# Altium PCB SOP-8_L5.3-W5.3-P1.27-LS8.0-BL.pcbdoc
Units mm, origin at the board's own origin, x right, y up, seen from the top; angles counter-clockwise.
Board outline 18.2 x 21.99 mm, 2 copper layers (Top Layer, Bottom Layer), stack 0 mm thick; 1 components, 0 nets, 8 pads, 0 vias.
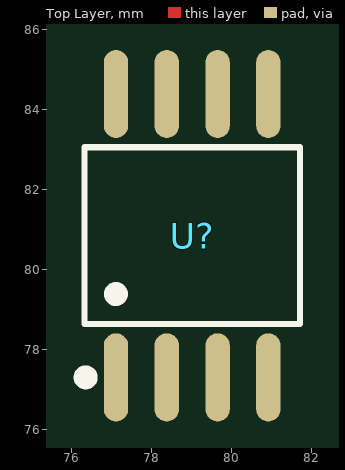
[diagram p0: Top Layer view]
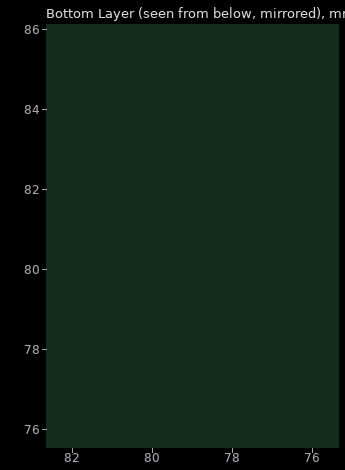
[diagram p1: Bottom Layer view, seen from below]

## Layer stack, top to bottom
Top Layer: signal copper (thickness not stored)
Bottom Layer: signal copper (thickness not stored)

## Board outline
88.053,69.85 69.85,69.85 69.85,91.839 88.053,91.839

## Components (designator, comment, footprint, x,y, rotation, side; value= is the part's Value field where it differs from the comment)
U? "" SOP-8_L5.3-W5.3-P1.27-LS8.0-BL 79.012,80.845 r0 top

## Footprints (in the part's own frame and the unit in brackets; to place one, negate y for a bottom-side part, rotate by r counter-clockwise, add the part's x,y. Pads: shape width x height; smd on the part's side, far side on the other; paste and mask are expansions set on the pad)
SOP-8_L5.3-W5.3-P1.27-LS8.0-BL [mm]
  oval 0.609x2.204 smd: 1(-1.905,-3.542) 2(-0.635,-3.542) 3(0.635,-3.542) 4(1.905,-3.542) 5(1.905,3.542) 6(0.635,3.542) 7(-0.635,3.542) 8(-1.905,3.542)
  silkscreen extent -2.81,-3.69 2.69,2.21

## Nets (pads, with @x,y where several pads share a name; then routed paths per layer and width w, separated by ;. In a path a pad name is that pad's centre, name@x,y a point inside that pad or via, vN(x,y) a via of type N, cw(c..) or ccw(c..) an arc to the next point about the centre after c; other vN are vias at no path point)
pads on no net: U?.1 U?.2 U?.3 U?.4 U?.5 U?.6 U?.7 U?.8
